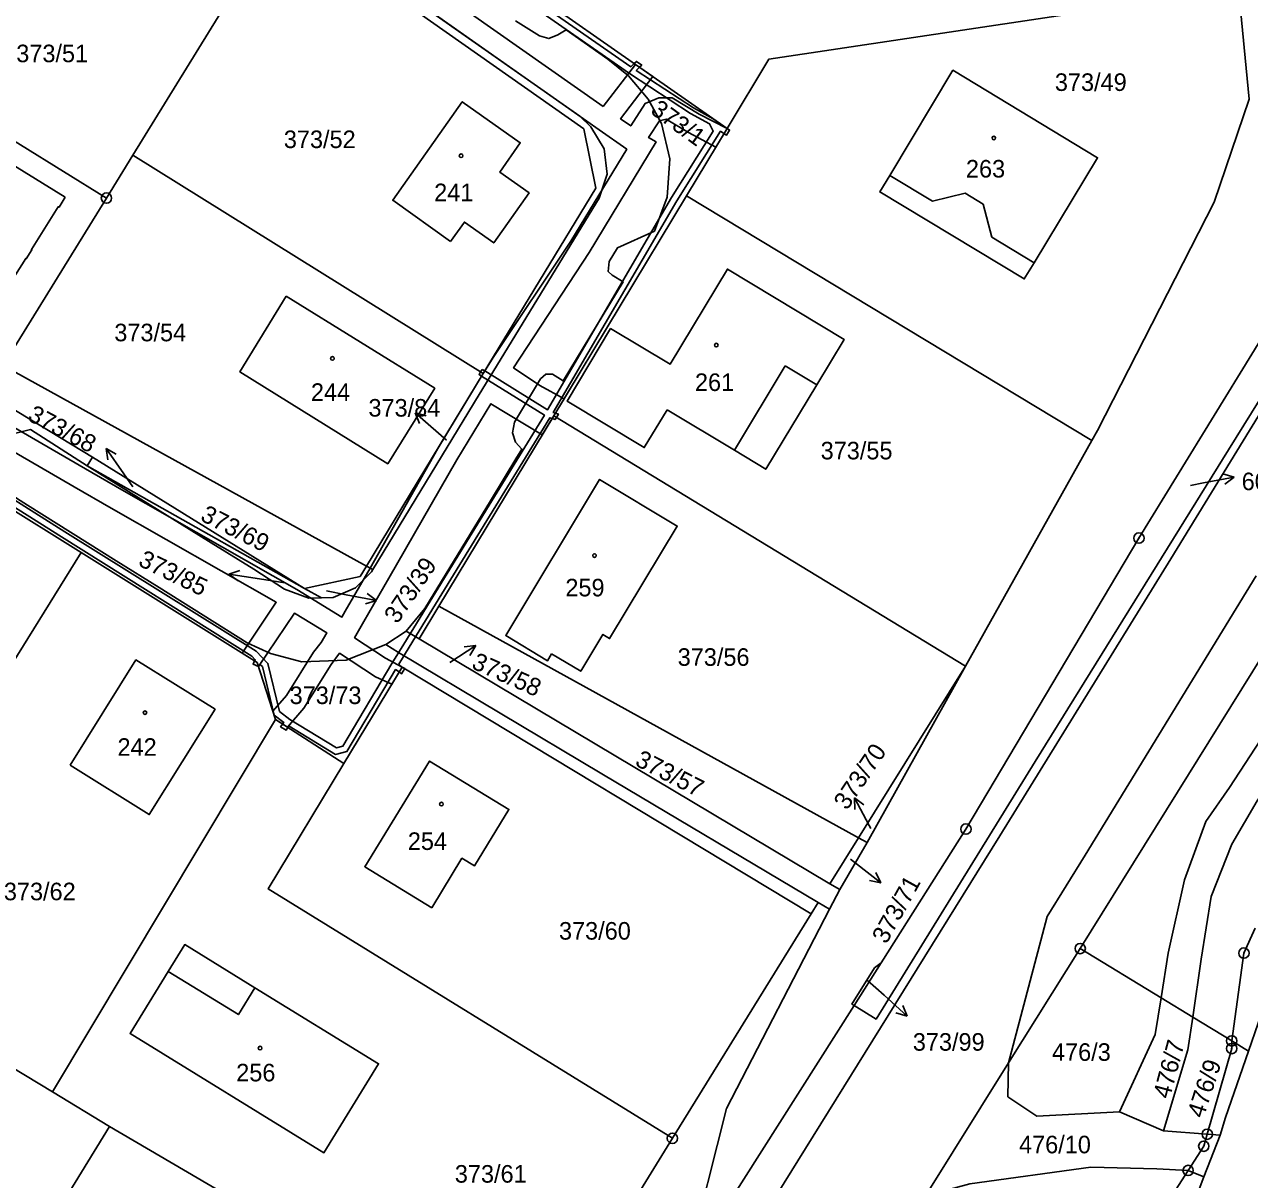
# Model space of a CAD drawing. Extents: x -758582 to -751794, y -998770 to -994350.
# Drawn here: x -754273.4 to -754154.9, y -996932.8 to -996821 of the extents above; entities that cross this region are included whole.
import ezdxf

# ---------------------------------------------------------------- set-up
doc = ezdxf.new("R2010")
doc.units = 0
for name, color, linetype in [('Hranice parcel', 7, 'Continuous'), ('Parcelní čísla', 7, 'Continuous'), ('Pop  PČ popisy', 7, 'Continuous'), ('Vnitřní kresba', 7, 'Continuous'), ('Věcná břemena k části', 7, 'Continuous'), ('Značky bodu BP', 7, 'Continuous'), ('Značky budov', 7, 'Continuous')]:
    doc.layers.add(name, color=color, linetype=linetype)

msp = doc.modelspace()

# ---------------------------------------------------------------- linework, layer by layer
at = {"layer": 'Hranice parcel'}
for p, q in [((-754262.93, -996833.65), (-754248.63, -996810.45)), ((-754205.42, -996831.06), (-754221.77, -996819.64)), ((-754209.35, -996837.58), (-754205.42, -996831.06)), ((-754265.49, -996837.81), (-754262.93, -996833.65)), ((-754262.93, -996833.65), (-754229.02, -996854.8)), ((-754275.49, -996854.02), (-754265.49, -996837.81)), ((-754222.2, -996858.88), (-754209.35, -996837.58)), ((-754209.35, -996837.58), (-754170.11, -996861.27)), ((-754275.49, -996854.02), (-754240.32, -996873.42)), ((-754240.32, -996873.42), (-754229.02, -996854.8)), ((-754277.12, -996856.67), (-754266.85, -996862.88)), ((-754233.31, -996877.3), (-754222.2, -996858.88)), ((-754222.2, -996858.88), (-754182.33, -996883.12)), ((-754267.95, -996872.12), (-754288.11, -996859.54)), ((-754170.11, -996861.27), (-754182.33, -996883.12)), ((-754266.85, -996862.88), (-754267.37, -996863.73)), ((-754246.31, -996875.58), (-754266.85, -996862.88)), ((-754267.37, -996863.73), (-754246.31, -996875.58)), ((-754267.95, -996872.12), (-754292.31, -996911.31)), ((-754239.7, -996873.76), (-754240.32, -996873.42)), ((-754246.31, -996875.58), (-754244.69, -996876.49)), ((-754235.22, -996880.46), (-754233.31, -996877.3)), ((-754233.31, -996877.3), (-754192.69, -996899.72)), ((-754236.48, -996879.71), (-754238.44, -996881.02)), ((-754236.48, -996879.71), (-754235.22, -996880.46)), ((-754235.22, -996880.46), (-754195.47, -996904.18)), ((-754192.69, -996899.72), (-754182.33, -996883.12)), ((-754182.33, -996883.12), (-754191.87, -996900.17)), ((-754249.13, -996888.29), (-754270.71, -996924.31)), ((-754242.5, -996892.52), (-754249.13, -996888.29)), ((-754195.47, -996904.18), (-754192.69, -996899.72)), ((-754191.87, -996900.17), (-754194.5, -996904.72)), ((-754192.69, -996899.72), (-754191.87, -996900.17)), ((-754194.5, -996904.72), (-754195.47, -996904.18)), ((-754194.5, -996904.72), (-754195.49, -996906.63)), ((-754196.59, -996905.97), (-754197.28, -996907.08)), ((-754195.49, -996906.63), (-754196.59, -996905.97)), ((-754197.28, -996907.08), (-754210.71, -996928.81)), ((-754154.96, -996920.37), (-754151.3, -996909.75)), ((-754171.24, -996910.44), (-754178.17, -996921.51)), ((-754163.41, -996915.21), (-754171.24, -996910.44)), ((-754193.13, -996915.94), (-754190.51, -996911.81)), ((-754211.2, -996944.43), (-754193.13, -996915.94)), ((-754163.41, -996915.21), (-754160.35, -996917.08)), ((-754160.35, -996917.08), (-754156.57, -996919.38)), ((-754270.71, -996924.31), (-754281.19, -996917.97)), ((-754154.96, -996920.37), (-754156.57, -996919.38)), ((-754186.22, -996934.38), (-754178.17, -996921.51)), ((-754265.19, -996927.65), (-754270.71, -996924.31)), ((-754167.45, -996926.24), (-754163.18, -996928.07)), ((-754271.31, -996937.63), (-754265.19, -996927.65)), ((-754249.07, -996937.1), (-754265.19, -996927.65)), ((-754163.18, -996928.07), (-754158.94, -996928.41)), ((-754210.71, -996928.81), (-754224.77, -996951.55))]:
    msp.add_line(p, q, dxfattribs=at)
for points in [[(-754239.7, -996873.76), (-754229.41, -996856.81), (-754217.8, -996837.82), (-754217.03, -996835.51), (-754217.32, -996833.04), (-754218.62, -996830.93), (-754219.67, -996829.87), (-754234.88, -996819.24), (-754238.87, -996816.4), (-754242.05, -996814.12), (-754242.11, -996811.52), (-754243.59, -996810.5), (-754244.68, -996810.77), (-754245.32, -996811.81), (-754254.42, -996805.34), (-754253.82, -996804.28), (-754253.75, -996803.63), (-754255.62, -996802.25), (-754263.11, -996799.25), (-754267.17, -996796.4), (-754276.31, -996789.92), (-754283.3, -996784.79), (-754285.08, -996783.85)], [(-754124.15, -996809.47), (-754125.24, -996811.23), (-754156.87, -996862.16), (-754175.6, -996892.33), (-754190.99, -996917.27), (-754193.13, -996915.94)], [(-754229.02, -996854.8), (-754218.13, -996836.86), (-754219.28, -996831.12), (-754248.63, -996810.45)], [(-754269.5, -996837.72), (-754291.96, -996823.84), (-754298.34, -996820.04), (-754303.19, -996817.16), (-754310.16, -996827.92), (-754305.29, -996830.99), (-754299.05, -996834.93), (-754276.49, -996848.83), (-754275.86, -996847.87), (-754275.94, -996847.8), (-754273.3, -996843.65), (-754273.25, -996843.68), (-754272.7, -996842.82), (-754272.75, -996842.78), (-754270.15, -996838.65), (-754270.08, -996838.7), (-754269.5, -996837.72)], [(-754287.28, -996817.78), (-754290.5, -996822.33), (-754265.49, -996837.81)], [(-754205.42, -996831.06), (-754201.37, -996824.36), (-754155.91, -996817.51)], [(-754155.91, -996817.51), (-754154.89, -996828.23), (-754158.27, -996838.22), (-754169.58, -996860.32), (-754170.11, -996861.27)], [(-754225.91, -996820.67), (-754223.58, -996822.12), (-754222.68, -996822.37), (-754221.79, -996822), (-754220.98, -996821.51), (-754216.95, -996824.36), (-754214.95, -996825.99), (-754213.07, -996828.25), (-754211.77, -996830.6), (-754210.96, -996834), (-754211.21, -996837.73), (-754212.46, -996841), (-754216.02, -996842.62), (-754216.84, -996843.96), (-754216.93, -996844.9), (-754216.55, -996845.26), (-754215.48, -996845.9), (-754221.29, -996855.5), (-754222.32, -996854.86), (-754222.96, -996854.85), (-754223.48, -996855.31), (-754225.98, -996859.49), (-754226.2, -996860.52), (-754225.89, -996861.44), (-754225.27, -996862.11), (-754225.78, -996862.9), (-754228.31, -996867.12), (-754234.22, -996876.8), (-754234.67, -996877.54), (-754236.48, -996879.71)], [(-754190.51, -996911.81), (-754182.3, -996898.88), (-754165.55, -996870.71), (-754154.64, -996852.92), (-754134.6, -996820.24)], [(-754175.7, -996844.07), (-754176.65, -996845.64), (-754190.64, -996837.22), (-754189.68, -996835.62), (-754183.56, -996825.43), (-754169.55, -996833.91), (-754175.7, -996844.07)], [(-754232.18, -996842), (-754237.78, -996838.02), (-754231.05, -996828.48), (-754225.44, -996832.46), (-754227.43, -996835.29), (-754224.59, -996837.31), (-754228, -996842.15), (-754230.85, -996840.14), (-754232.18, -996842)], [(-754125.03, -996836.29), (-754127.48, -996840.18), (-754171.24, -996910.44)], [(-754163.41, -996915.21), (-754162.71, -996910.9), (-754161.15, -996903.8), (-754159.07, -996898.16), (-754156.78, -996894.86), (-754125.98, -996847.67), (-754122.48, -996842.64)], [(-754211.23, -996858.29), (-754213.43, -996861.95), (-754220.91, -996857.45), (-754216.69, -996850.44), (-754210.94, -996853.9), (-754205.39, -996844.68), (-754194.09, -996851.49), (-754196.74, -996855.9), (-754201.67, -996864.05), (-754204.71, -996862.22), (-754211.23, -996858.29)], [(-754160.35, -996917.08), (-754159.53, -996911.47), (-754158.56, -996905.42), (-754156.57, -996900.34), (-754154.12, -996896.15), (-754123.97, -996849.99), (-754119.46, -996845.06)], [(-754248.09, -996847.31), (-754233.72, -996856.21), (-754238.26, -996863.53), (-754252.57, -996854.63), (-754248.09, -996847.31)], [(-754284.25, -996853.14), (-754276.22, -996858.14), (-754277.04, -996859.34), (-754276.76, -996860.27), (-754275.43, -996860.84), (-754272.85, -996860.22), (-754267.37, -996863.73)], [(-754267.37, -996863.73), (-754255.36, -996871.16), (-754251.23, -996873.74), (-754248.25, -996875.65), (-754245.91, -996876.53), (-754244.69, -996876.49)], [(-754238.44, -996881.02), (-754242.3, -996882.52), (-754246.58, -996882.68), (-754249.62, -996881.88), (-754251.88, -996880.85), (-754260.4, -996875.49), (-754264.55, -996872.91), (-754273.14, -996867.52), (-754277.26, -996864.91)], [(-754222.4, -996881.93), (-754222.79, -996882.59), (-754226.84, -996880.15), (-754217.76, -996865.04), (-754210.25, -996869.56), (-754216.79, -996880.44), (-754217.44, -996880.04), (-754219.59, -996883.61), (-754222.4, -996881.93)], [(-754249.13, -996888.29), (-754250.89, -996882.77), (-754267.95, -996872.12)], [(-754240.32, -996873.42), (-754240.94, -996874.44), (-754246.31, -996875.58)], [(-754244.69, -996876.49), (-754243.56, -996876.46), (-754241.37, -996875.53), (-754239.82, -996873.97), (-754239.7, -996873.76)], [(-754238.44, -996881.02), (-754237.22, -996881.8), (-754217.53, -996893.52), (-754196.59, -996905.97)], [(-754269, -996892.68), (-754262.64, -996882.5), (-754254.98, -996887.29), (-754261.35, -996897.47), (-754269, -996892.68)], [(-754197.28, -996907.08), (-754236.88, -996883.2), (-754242.5, -996892.52)], [(-754242.5, -996892.52), (-754249.83, -996904.67), (-754210.71, -996928.81)], [(-754234, -996906.51), (-754240.49, -996902.53), (-754234.22, -996892.3), (-754226.54, -996896.97), (-754229.88, -996902.45), (-754231.08, -996901.7), (-754234, -996906.51)], [(-754195.49, -996906.63), (-754205.49, -996925.91), (-754209.12, -996940.39), (-754211.2, -996944.43)], [(-754154.3, -996908.48), (-754155.39, -996910.88), (-754156.57, -996919.38)], [(-754259.52, -996912.67), (-754257.92, -996910.06), (-754251.12, -996914.23), (-754239.15, -996921.6), (-754244.44, -996930.21), (-754263.2, -996918.68), (-754259.52, -996912.67)], [(-754193.13, -996915.94), (-754193.34, -996915.81), (-754191.14, -996912.32), (-754190.51, -996911.81)], [(-754167.45, -996926.24), (-754163.98, -996918.75), (-754163.41, -996915.21)], [(-754163.18, -996928.07), (-754160.82, -996920.26), (-754160.35, -996917.08)], [(-754156.57, -996919.38), (-754156.57, -996920.12), (-754158.94, -996928.41)], [(-754203.34, -996967.22), (-754191.72, -996948.22), (-754161.36, -996938.09), (-754159.26, -996932.55), (-754157.69, -996928.51), (-754157.17, -996926.8), (-754154.96, -996920.37)], [(-754178.17, -996921.51), (-754178.24, -996924.79), (-754175.44, -996926.65), (-754167.45, -996926.24)], [(-754158.94, -996928.41), (-754159.28, -996929.57), (-754160.79, -996931.92)], [(-754186.22, -996934.38), (-754181.92, -996933.2), (-754170.21, -996931.59), (-754163.83, -996931.75), (-754160.79, -996931.92)], [(-754160.79, -996931.92), (-754163.75, -996936.54), (-754170.94, -996940.64), (-754179, -996941.08), (-754187.22, -996937.45), (-754187.94, -996937.12)]]:
    msp.add_lwpolyline(points, dxfattribs=at)
at = {"layer": 'Pop  PČ popisy'}
for p, q in [((-754233.35, -996860.57), (-754235.61, -996858.6)), ((-754235.61, -996858.6), (-754234.53, -996858.88)), ((-754235.61, -996858.6), (-754235.19, -996859.64)), ((-754232.59, -996861.23), (-754233.35, -996860.57)), ((-754263.81, -996864.5), (-754265.53, -996862.04)), ((-754265.53, -996862.04), (-754264.55, -996862.58)), ((-754265.53, -996862.04), (-754265.37, -996863.15)), ((-754262.95, -996865.75), (-754263.81, -996864.5)), ((-754159.29, -996865.38), (-754156.34, -996864.81)), ((-754156.34, -996864.81), (-754157.42, -996864.51)), ((-754156.34, -996864.81), (-754157.23, -996865.49)), ((-754160.56, -996865.63), (-754159.29, -996865.38)), ((-754253.64, -996874.2), (-754252.58, -996873.86)), ((-754250.68, -996874.67), (-754253.64, -996874.2)), ((-754253.64, -996874.2), (-754252.73, -996874.85)), ((-754248.21, -996875.05), (-754250.68, -996874.67)), ((-754244.2, -996875.83), (-754242.3, -996876.2)), ((-754242.3, -996876.2), (-754239.35, -996876.77)), ((-754239.35, -996876.77), (-754240.43, -996877.07)), ((-754239.35, -996876.77), (-754240.24, -996876.09)), ((-754232.26, -996882.75), (-754229.74, -996881.12)), ((-754229.74, -996881.12), (-754230.86, -996881.24)), ((-754229.74, -996881.12), (-754230.31, -996882.08)), ((-754191.67, -996898.52), (-754193.08, -996895.87)), ((-754193.08, -996895.87), (-754192.17, -996896.52)), ((-754193.08, -996895.87), (-754193.05, -996896.99)), ((-754191.51, -996898.81), (-754191.67, -996898.52)), ((-754193.47, -996901.78), (-754192.89, -996902.23)), ((-754192.89, -996902.23), (-754190.53, -996904.08)), ((-754190.53, -996904.08), (-754191.01, -996903.07)), ((-754190.53, -996904.08), (-754191.62, -996903.86)), ((-754191.83, -996913.53), (-754190.23, -996914.97)), ((-754190.23, -996914.97), (-754188, -996916.98)), ((-754188, -996916.98), (-754188.41, -996915.94)), ((-754188, -996916.98), (-754189.08, -996916.68))]:
    msp.add_line(p, q, dxfattribs=at)
at = {"layer": 'Vnitřní kresba'}
for p, q in [((-754131.23, -996821.61), (-754162.46, -996872.74)), ((-754189.68, -996835.62), (-754185.55, -996838.12)), ((-754185.55, -996838.12), (-754182.38, -996837.33)), ((-754182.38, -996837.33), (-754180.62, -996838.4)), ((-754180.62, -996838.4), (-754179.8, -996841.59)), ((-754179.8, -996841.59), (-754175.7, -996844.07)), ((-754204.71, -996862.22), (-754199.79, -996854.06)), ((-754199.79, -996854.06), (-754196.74, -996855.9)), ((-754162.46, -996872.74), (-754179.03, -996899.53)), ((-754154.22, -996874.38), (-754170.76, -996901.39)), ((-754179.03, -996899.53), (-754246.61, -997008.22)), ((-754170.76, -996901.39), (-754174.45, -996907.34)), ((-754174.45, -996907.34), (-754178.17, -996921.51)), ((-754157.69, -996928.51), (-754158.94, -996928.41)), ((-754159.26, -996932.55), (-754160.79, -996931.92))]:
    msp.add_line(p, q, dxfattribs=at)
msp.add_lwpolyline([(-754259.52, -996912.67), (-754252.71, -996916.84), (-754251.12, -996914.23)], dxfattribs=at)
at = {"layer": 'Věcná břemena k části'}
for points in [[(-754280.96, -996786.66), (-754272.55, -996792.46), (-754272.96, -996793.32), (-754269.57, -996795.71), (-754269.02, -996794.93), (-754267.32, -996796.08), (-754245.6, -996811.76), (-754241.09, -996815.18), (-754236.9, -996817.76), (-754217.79, -996831.19), (-754215.13, -996833.09), (-754220.53, -996841.99), (-754228.01, -996853.13), (-754229.02, -996854.8), (-754233.42, -996862.05), (-754239.97, -996873.62), (-754242.37, -996877.79), (-754242.7, -996878.37), (-754247.05, -996875.69), (-754264, -996866.04), (-754267.53, -996864), (-754282.61, -996855.27)], [(-754217.41, -996828.94), (-754235.77, -996816.04), (-754239.92, -996813.48), (-754243.75, -996810.58), (-754242.66, -996809.23), (-754240.82, -996806.32), (-754244.23, -996803.94), (-754246.13, -996806.16), (-754247.69, -996807.71), (-754266.14, -996794.39)], [(-754208.67, -996829.09), (-754214.21, -996825.45), (-754213.9, -996825.14), (-754213.68, -996824.93), (-754214.18, -996824.58), (-754214.4, -996824.79), (-754214.72, -996825.1), (-754242.57, -996805.72)], [(-754243.19, -996806.03), (-754214.86, -996825.74), (-754208.97, -996829.61), (-754207.12, -996830.61), (-754206.75, -996831.34), (-754210.79, -996837.74), (-754222.79, -996858.29), (-754228.86, -996854.54), (-754229.02, -996854.8), (-754229.18, -996855.06), (-754223.1, -996858.81), (-754234.16, -996876.83), (-754236.71, -996880.98), (-754237.86, -996882.85), (-754242.6, -996890.85), (-754243.22, -996891.01), (-754247.73, -996888.26), (-754248.74, -996887.5), (-754249.86, -996882.84), (-754251.01, -996881.67), (-754269.52, -996870.11), (-754287.69, -996858.64)], [(-754284.05, -996856.82), (-754268.6, -996865.76), (-754265.03, -996867.83), (-754249.05, -996876.92), (-754252.37, -996881.84), (-754250.89, -996882.77), (-754250.77, -996883.16), (-754247.28, -996877.97), (-754244.17, -996879.88), (-754244.71, -996880.82), (-754245.44, -996881.76), (-754248.07, -996885.96), (-754249.39, -996887.47), (-754249.13, -996888.29), (-754247.97, -996889.03), (-754246.4, -996887.18), (-754243.75, -996882.94), (-754242.92, -996881.87), (-754239.46, -996884.15), (-754237.88, -996884.86), (-754236.88, -996883.2), (-754238.47, -996882.34), (-754241.48, -996880.36), (-754240.58, -996878.8), (-754238.17, -996874.61), (-754231.57, -996863.15), (-754228.27, -996857.72), (-754223.32, -996860.73), (-754221.2, -996857.23), (-754223.53, -996855.94), (-754226.09, -996854.23), (-754218.78, -996843.09), (-754212.29, -996832.38), (-754213.02, -996831.95), (-754211.97, -996830.32), (-754211.3, -996830.16), (-754209.15, -996831.47), (-754206.52, -996832.88), (-754205.42, -996831.06), (-754208.13, -996829.68), (-754210.73, -996828.1), (-754212.01, -996828.1), (-754213.36, -996828.67), (-754214.75, -996830.83), (-754215.73, -996830.13), (-754212.59, -996826.05), (-754214.28, -996824.87), (-754217.41, -996828.94)], [(-754287.71, -996859.34), (-754269.84, -996870.61), (-754251.41, -996882.13), (-754251.09, -996882.49), (-754251.15, -996882.61), (-754250.89, -996882.77), (-754250.77, -996883.16), (-754250.64, -996882.94), (-754250.4, -996883.16), (-754249.27, -996887.86), (-754248.32, -996888.57), (-754248.44, -996888.73), (-754248.63, -996888.97), (-754248.1, -996889.31), (-754247.92, -996889.06), (-754247.82, -996888.91), (-754243.32, -996891.65), (-754242.22, -996891.37), (-754237.51, -996883.44), (-754237.17, -996883.67), (-754236.92, -996883.85), (-754236.62, -996883.35), (-754236.88, -996883.2), (-754237.2, -996882.92), (-754236.18, -996881.27), (-754233.63, -996877.12), (-754222.56, -996859.07), (-754222.36, -996859.14), (-754222.07, -996859.24), (-754221.94, -996859.04), (-754221.75, -996858.72), (-754222.04, -996858.62), (-754222.25, -996858.55), (-754210.27, -996838.06), (-754206.04, -996831.34), (-754205.72, -996831.55), (-754205.47, -996831.72), (-754205.17, -996831.23), (-754205.42, -996831.06), (-754206.76, -996830.13), (-754208.67, -996829.09)]]:
    msp.add_lwpolyline(points, dxfattribs=at)
for points in [[(-754229.12, -996854.39), (-754229.27, -996854.64), (-754229.02, -996854.8), (-754228.86, -996854.54)], [(-754229.27, -996854.64), (-754229.43, -996854.9), (-754229.18, -996855.06), (-754229.02, -996854.8)], [(-754251.15, -996882.61), (-754251.29, -996882.92), (-754250.77, -996883.16), (-754250.89, -996882.77)]]:
    msp.add_lwpolyline(points, close=True, dxfattribs=at)
at = {"layer": 'Značky bodu BP'}
for centre, radius in [((-754265.49, -996837.81), 0.5), ((-754265.49, -996837.81), 0.0303), ((-754165.55, -996870.71), 0.5), ((-754165.55, -996870.71), 0.0303), ((-754182.3, -996898.88), 0.5), ((-754182.3, -996898.88), 0.0303), ((-754171.24, -996910.44), 0.5), ((-754171.24, -996910.44), 0.0303), ((-754155.39, -996910.88), 0.5), ((-754155.39, -996910.88), 0.0303), ((-754156.57, -996919.38), 0.5), ((-754156.57, -996920.12), 0.5), ((-754156.57, -996919.38), 0.0303), ((-754156.57, -996920.12), 0.0303), ((-754158.94, -996928.41), 0.5), ((-754210.71, -996928.81), 0.5), ((-754210.71, -996928.81), 0.0303), ((-754159.28, -996929.57), 0.5), ((-754158.94, -996928.41), 0.0303), ((-754159.28, -996929.57), 0.0303), ((-754160.79, -996931.92), 0.5), ((-754160.79, -996931.92), 0.0303)]:
    msp.add_circle(centre, radius, dxfattribs=at)
at = {"layer": 'Značky budov'}
for centre in [(-754179.6, -996831.99), (-754231.16, -996833.71), (-754206.46, -996852.04), (-754243.62, -996853.33), (-754218.25, -996872.41), (-754261.76, -996887.61), (-754233.07, -996896.46), (-754250.62, -996920.08)]:
    msp.add_circle(centre, 0.175, dxfattribs=at)

# ---------------------------------------------------------------- texts
at = {"layer": 'Parcelní čísla'}
for s, p in [('373/51', (-754274.22, -996824.66)), ('373/49', (-754173.69, -996827.44)), ('373/52', (-754248.32, -996832.97)), ('263', (-754182.3, -996835.82)), ('241', (-754233.77, -996838.11)), ('373/54', (-754264.73, -996851.67)), ('244', (-754245.7, -996857.44)), ('261', (-754208.53, -996856.48)), ('373/84', (-754240.13, -996858.96)), ('373/55', (-754196.36, -996863.1)), ('608/5', (-754155.61, -996866.08)), ('259', (-754221.07, -996876.36)), ('373/56', (-754210.2, -996883.08)), ('373/73', (-754247.76, -996886.78)), ('242', (-754264.42, -996891.79)), ('254', (-754236.32, -996900.9)), ('373/62', (-754275.42, -996905.77)), ('373/60', (-754221.69, -996909.58)), ('373/99', (-754187.44, -996920.33)), ('476/3', (-754173.97, -996921.31)), ('256', (-754252.93, -996923.3)), ('476/10', (-754177.16, -996930.26)), ('373/61', (-754231.77, -996933.1))]:
    msp.add_text(s, height=1.7, dxfattribs=at).set_placement(p)
for s, rotation, p in [('373/1', 324, (-754212.93, -996829.54)), ('373/68', 332, (-754273.22, -996859.26)), ('373/69', 333, (-754256.5, -996868.96)), ('373/85', 334, (-754262.51, -996873.33)), ('373/39', 56, (-754237.33, -996879.1)), ('373/58', 336, (-754230.25, -996883.28)), ('373/57', 333, (-754214.43, -996892.67)), ('373/70', 56, (-754193.81, -996897.13)), ('373/71', 61, (-754190, -996910.09)), ('476/7', 75, (-754162.58, -996925.07)), ('476/9', 72, (-754159.31, -996926.94))]:
    msp.add_text(s, height=1.7, rotation=rotation, dxfattribs=at).set_placement(p)

doc.saveas('drawing.dxf')
